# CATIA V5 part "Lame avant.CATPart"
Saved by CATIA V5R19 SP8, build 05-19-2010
Part number: Lame avant
Bounding box of the stored display mesh (mm): x 0 to 670, y -7.5 to 7.5, z 0 to 15
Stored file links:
  G:\EU_thinkMotion\CFAO_2010\MMS_groupe2\MMS_groupe2\A reprendre\rbouchet\rbouchet_Catia\Lame avant.CATPart
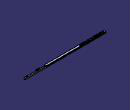
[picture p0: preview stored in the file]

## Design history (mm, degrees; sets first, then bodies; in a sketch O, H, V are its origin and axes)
Body1 (main body)
  Sketch1 on yz-plane, origin (0, 0, 0), H (0, 1, 0), V (0, 0, 1)
    line L1 (-4.5, 10) -> (-4.5, 0)
    point P1 (-4.5, 0)
    line L2 (-4.5, 0) -> (4.5, 0)
    line L3 (4.5, 0) -> (4.5, 10)
    line L4 (4.5, 10) -> (7.5, 10)
    line L5 (7.5, 15) -> (7.5, 10)
    line L6 (7.5, 15) -> (-7.5, 15)
    line L7 (-7.5, 15) -> (-7.5, 10)
    point P8 (-7.5, 10)
    line L8 (-7.5, 10) -> (-4.5, 10)
    length L2 = 9
    length L8 = 3
    length L4 = 3
    length L3 = 10
    length L5 = 5
    distance V L3 = 4.5
    coincidence: P1 H, P8 L4
    vertical: L1 V, L3 V, L5 V, L7 V
    horizontal: L2 H, L4 H, L6 H, L8 H
  Pad1: profile Sketch1, direction (1, 0, 0), length 670
  Sketch2 on face of Pad1 from Sketch1.L6, origin (0, 0, 15), H (1, 0, 0), V (0, 1, 0)
    line L1 (492.5838, -7.5) -> (500, -4.5)
    point P1 (492.5838, -7.5)
    line L2 (500, -4.5) -> (670, -4.5)
    point P3 (670, -4.5)
    reference projected line E1 (670, 7.5) -> (670, -7.5) from edge [face of Pad1 from Sketch1.L6 | end face of Pad1]
    reference projected line E2 (0, -7.5) -> (670, -7.5) from edge [face of Pad1 from Sketch1.L7 | face of Pad1 from Sketch1.L6]
    reference projected line E3 (0, -7.5) -> (670, -7.5) from edge [face of Pad1 from Sketch1.L7 | face of Pad1 from Sketch1.L6]
    length L2 = 170
    length L1 = 8
    distance L2 E3 = 3
    horizontal: L2 H
    coincidence: P3 E1, P1 E2
  Pocket1: profile Sketch2, direction (0, 0, -1), length 670
  Sketch3 on face of Pad1 from Sketch1.L6, origin (0, 0, 15), H (1, 0, 0), V (0, 1, 0)
    line L1 (492.5838, 7.5) -> (500, 4.5)
    point P1 (492.5838, 7.5)
    point P2 (500, 4.5)
    line L2 (500, 4.5) -> (670, 4.5)
    point P3 (500, 4.5)
    point P4 (670, 4.5)
    reference projected line E1 (670, 7.5) -> (670, -7.5) from edge [face of Pad1 from Sketch1.L6 | end face of Pad1]
    reference projected line E2 (0, 7.5) -> (670, 7.5) from edge [face of Pad1 from Sketch1.L6 | face of Pad1 from Sketch1.L5]
    reference projected line E3 (0, 7.5) -> (670, 7.5) from edge [face of Pad1 from Sketch1.L6 | face of Pad1 from Sketch1.L5]
    length L2 = 170
    distance L2 E2 = 3
    length L1 = 8
    horizontal: L2 H
    coincidence: P4 E1, P2 P3, E3 P1
  Pocket2: profile Sketch3, direction (0, 0, -1), length 670
  Sketch4 on face of Pad1 from Sketch1.L6, origin (0, 0, 15), H (1, 0, 0), V (0, 1, 0)
    line L1 (500, 4.5) -> (500, 2.5)
    point P1 (500, 4.5)
    line L2 (500, 2.5) -> (505, 2.5)
    line L3 (505, 2.5) -> (505, -2.5)
    line L4 (505, -2.5) -> (500, -2.5)
    point P5 (500, -2.5)
    line L5 (500, -2.5) -> (500, -4.5)
    point P6 (500, -4.5)
    reference projected line E1 (500, 4.5) -> (670, 4.5) from edge [face of Pad1 from Sketch1.L6 | face of Pocket2]
    reference projected line E2 (670, -4.5) -> (500, -4.5) from edge [face of Pad1 from Sketch1.L6 | face of Pocket1]
    reference projected point E3 (500, 4.5) from vertex [face of Pocket2 from Sketch3.L1 | face of Pocket2 | face of Pad1 from Sketch1.L6]
    length L2 = 5
    length L3 = 5
    length L1 = 2
    vertical: L1 V, L3 V, L5 V
    horizontal: L2 H, L4 H
    coincidence: P5 L1, P1 E1, P6 E2, P1 E3
  Pocket3: profile Sketch4, direction (0, 0, -1), length 5
  Sketch5 on end face of Pocket3, origin (603.9517, -3.6994, 10), H (1, 0, 0), V (0, 1, 0)
    point P1 (46.0483, 3.6994)
    reference projected line E1 (66.0483, 8.1994) -> (-103.9517, 8.1994) from edge [face of Pocket2 | end face of Pocket3]
    reference intersected line E2 (-103.9517, 6.1994) -> (-103.9517, 8.1994) from face of Pocket3 from Sketch4.L1
    distance P1 E1 = 4.5
    distance P1 E2 = 150
  Hole1: placed by Sketch5, at (650, 0, 10) direction (0, 0, -1), diameter 8, through (limit type 6)
  Sketch6 on face of Pad1 from Sketch1.L6, origin (0, 0, 15), H (1, 0, 0), V (0, 1, 0)
    line L1 (5, 7.5) -> (5, -7.5)
    point P1 (5, 7.5)
    point P2 (5, -7.5)
    reference projected line E1 (0, 7.5) -> (670, 7.5) from edge [face of Pad1 from Sketch1.L6 | face of Pad1 from Sketch1.L5]
    reference projected line E2 (0, -7.5) -> (670, -7.5) from edge [face of Pad1 from Sketch1.L7 | face of Pad1 from Sketch1.L6]
    reference projected line E3 (0, 7.5) -> (0, -7.5) from edge [start face of Pad1 | face of Pad1 from Sketch1.L6]
    reference projected line E4 (0, 7.5) -> (0, -7.5) from edge [start face of Pad1 | face of Pad1 from Sketch1.L6]
    distance E4 L1 = 5
    vertical: L1 V
    coincidence: P1 E1, P2 E2
    parallelism: L1 E3
  Pocket4: profile Sketch6, direction (0, 0, -1), length 10
  Fillet1: radius 1, on edge [start face of Pad1 | face of Pocket1]; edge [start face of Pad1 | face of Pocket2]; edge [face of Pocket3 from Sketch4.L2 | face of Pocket3 from Sketch4.L1]; edge [face of Pocket3 from Sketch4.L3 | face of Pocket3 from Sketch4.L2]; edge [face of Pocket3 from Sketch4.L4 | face of Pocket3 from Sketch4.L3]; edge [face of Pocket3 from Sketch4.L5 | face of Pocket3 from Sketch4.L4]; edge [face of Pocket1 from Sketch2.L1 | face of Pocket3 from Sketch4.L5]; edge [face of Pad1 from Sketch1.L7 | face of Pocket1 from Sketch2.L1]; edge [face of Pocket3 from Sketch4.L1 | face of Pocket2 from Sketch3.L1]; edge [face of Pocket2 from Sketch3.L1 | face of Pad1 from Sketch1.L5]
  Sketch7 on face of Pad1 from Sketch1.L6, origin (0, 0, 15), H (1, 0, 0), V (0, 1, 0)
    line L1 (15, 4) -> (21.875, 4)
    line L2 (21.875, 4) -> (21.875, -4)
    line L3 (21.875, -4) -> (15, -4)
    line L4 (15, -4) -> (15, 4)
    reference projected line E1 (0, 7.5) -> (670, 7.5) from edge [face of Pad1 from Sketch1.L6 | face of Pad1 from Sketch1.L5]
    reference projected line E2 (5, 7.5) -> (5, -7.5) from edge [face of Pocket4 from Sketch6.L1 | face of Pad1 from Sketch1.L6]
    length L2 = 8
    length L3 = 6.875
    distance L1 E1 = 3.5
    distance E2 L4 = 10
    horizontal: L1 H, L3 H
    vertical: L2 V, L4 V
  Pocket5: profile Sketch7, direction (0, 0, -1), length 8
  Fillet2: radius 1, on edge [face of Pocket5 from Sketch7.L3 | face of Pocket5 from Sketch7.L4]; edge [face of Pocket5 from Sketch7.L2 | face of Pocket5 from Sketch7.L3]; edge [face of Pocket5 from Sketch7.L4 | face of Pocket5 from Sketch7.L1]; edge [face of Pocket5 from Sketch7.L1 | face of Pocket5 from Sketch7.L2]
  RectPattern1: of Pocket5, Fillet2, direction 1 instances 16, spacing 12.875, along edge [face of Pad1 from Sketch1.L7 | face of Pad1 from Sketch1.L6]
  Sketch8 on end face of Pocket3, origin (0, 0, 10), H (1, 0, 0), V (0, 1, 0)
    line L1 (540, -2.5) -> (570, -2.5)
    line L2 (570, -2.5) -> (570, -7.5)
    line L3 (570, -7.5) -> (540, -7.5)
    line L4 (540, -7.5) -> (540, -2.5)
    reference intersected line E1 (500, -4.5) -> (500, -2.5) from face of Pocket3 from Sketch4.L5
    reference projected line E2 (500, -4.5) -> (670, -4.5) from edge [face of Pocket1 | end face of Pocket3]
    length L2 = 5
    length L1 = 30
    distance L4 E1 = 40
    distance L1 E2 = 2
    horizontal: L1 H, L3 H
    vertical: L2 V, L4 V
  Pad2: profile Sketch8, direction (0, 0, -1), length 10, opposite side length 5
  Fillet3: radius 1, on edge [face of Pad2 from Sketch8.L1 | face of Pad2 from Sketch8.L4]; edge [face of Pad2 from Sketch8.L2 | face of Pad2 from Sketch8.L1]; edge [face of Pad2 from Sketch8.L4 | face of Pad2 from Sketch8.L3]; edge [face of Pad2 from Sketch8.L3 | face of Pad2 from Sketch8.L2]; edge [face of Pocket1 | face of Pad2 from Sketch8.L2]; edge [face of Pad2 from Sketch8.L4 | face of Pocket1]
